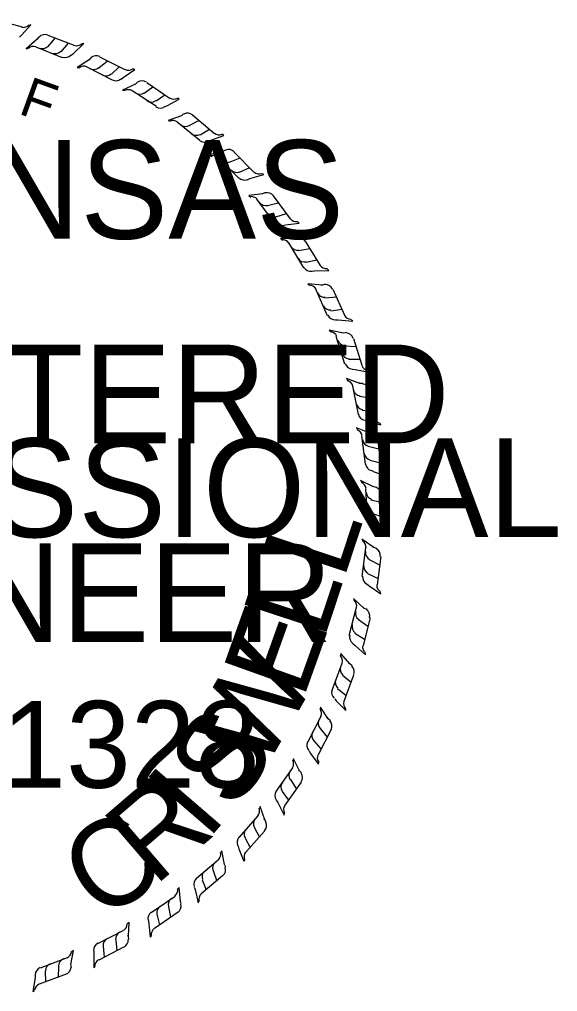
# Model space of a CAD drawing. Extents: x -193 to 149, y 507 to 725.
# Drawn here: x 66.24 to 76.47, y 521.36 to 539.84 of the extents above; entities that cross this region are included whole.
import ezdxf

# ---------------------------------------------------------------- set-up
doc = ezdxf.new("R2010")
doc.units = 0
doc.layers.add('Border 2660-Hwy18 - Stamp-ChrisC', color=7, linetype='Continuous')

msp = doc.modelspace()

# ---------------------------------------------------------------- linework, layer by layer
at = {"layer": 'Border 2660-Hwy18 - Stamp-ChrisC'}
for p, q in [((65.767, 539.835), (66.292, 539.693)), ((66.277, 539.535), (66.457, 539.73)), ((66.457, 539.73), (66.427, 539.723)), ((66.24, 539.498), (66.277, 539.535)), ((66.577, 539.46), (66.367, 539.28)), ((66.577, 539.46), (66.562, 539.445)), ((66.607, 539.505), (66.577, 539.46)), ((66.78, 539.535), (67.29, 539.34)), ((66.78, 539.318), (66.922, 539.483)), ((67.035, 539.22), (67.17, 539.385)), ((66.367, 539.28), (66.42, 539.295)), ((67.057, 539.108), (66.555, 539.31)), ((67.267, 539.19), (67.462, 539.378)), ((67.462, 539.378), (67.425, 539.37)), ((67.23, 539.16), (67.267, 539.19)), ((67.567, 539.07), (67.335, 538.92)), ((67.567, 539.07), (67.537, 539.055)), ((67.597, 539.108), (67.567, 539.07)), ((67.747, 538.913), (67.912, 539.048)), ((67.762, 539.123), (68.242, 538.883)), ((67.335, 538.92), (67.387, 538.913)), ((68.01, 538.68), (67.515, 538.935)), ((67.987, 538.793), (68.137, 538.935)), ((68.212, 538.733), (68.43, 538.883)), ((68.43, 538.883), (68.392, 538.898)), ((68.175, 538.703), (68.212, 538.733)), ((68.482, 538.643), (68.445, 538.605)), ((68.445, 538.605), (68.197, 538.493)), ((68.197, 538.493), (68.242, 538.485)), ((68.842, 538.178), (68.385, 538.478)), ((68.445, 538.605), (68.422, 538.598)), ((68.61, 538.433), (68.775, 538.553)), ((68.662, 538.635), (69.105, 538.335)), ((68.835, 538.29), (69, 538.403)), ((69.052, 538.2), (69.277, 538.32)), ((69.277, 538.32), (69.247, 538.343)), ((69.007, 538.178), (69.052, 538.2)), ((69.322, 538.005), (69.067, 537.915)), ((69.067, 537.915), (69.112, 537.9)), ((69.322, 538.005), (69.3, 537.998)), ((69.36, 538.043), (69.322, 538.005)), ((69.465, 537.818), (69.652, 537.915)), ((69.532, 538.02), (69.945, 537.668)), ((69.667, 537.533), (69.24, 537.885)), ((69.675, 537.645), (69.855, 537.75)), ((69.832, 537.518), (69.877, 537.54)), ((69.877, 537.54), (70.125, 537.63)), ((70.125, 537.63), (70.095, 537.653)), ((70.155, 537.353), (70.11, 537.33)), ((70.11, 537.33), (69.855, 537.263)), ((69.855, 537.263), (69.9, 537.233)), ((70.41, 536.82), (70.02, 537.218)), ((70.11, 537.33), (70.087, 537.315)), ((70.245, 537.128), (70.432, 537.203)), ((70.32, 537.315), (70.695, 536.933)), ((70.425, 536.933), (70.62, 537.023)), ((70.575, 536.79), (70.62, 536.813)), ((70.62, 536.813), (70.882, 536.888)), ((70.882, 536.888), (70.852, 536.903)), ((70.86, 536.52), (70.597, 536.49)), ((70.597, 536.49), (70.635, 536.46)), ((70.86, 536.52), (70.837, 536.513)), ((70.905, 536.543), (70.86, 536.52)), ((71.062, 536.483), (71.385, 536.048)), ((71.085, 535.973), (70.755, 536.423)), ((70.957, 536.303), (71.16, 536.348)), ((71.115, 536.085), (71.317, 536.145)), ((71.242, 535.92), (71.295, 535.935)), ((71.295, 535.935), (71.557, 535.965)), ((71.557, 535.965), (71.527, 535.995)), ((71.52, 535.695), (71.475, 535.673)), ((71.475, 535.673), (71.205, 535.673)), ((71.205, 535.673), (71.242, 535.635)), ((71.647, 535.118), (71.362, 535.59)), ((71.475, 535.673), (71.445, 535.68)), ((71.67, 535.62), (71.955, 535.163)), ((71.55, 535.448), (71.76, 535.485)), ((71.692, 535.223), (71.895, 535.268)), ((71.805, 535.05), (71.85, 535.058)), ((71.85, 535.058), (72.12, 535.065)), ((72.12, 535.065), (72.09, 535.095)), ((72, 534.788), (71.722, 534.81)), ((71.722, 534.81), (71.767, 534.78)), ((72, 534.788), (71.97, 534.788)), ((72.06, 534.803), (72, 534.788)), ((72.097, 534.203), (71.872, 534.713)), ((72.195, 534.713), (72.42, 534.218)), ((72.045, 534.548), (72.27, 534.563)), ((72.157, 534.3), (72.375, 534.33)), ((72.255, 534.128), (72.3, 534.128)), ((72.3, 534.128), (72.577, 534.105)), ((72.577, 534.105), (72.547, 534.135)), ((72.397, 533.873), (72.127, 533.933)), ((72.127, 533.933), (72.172, 533.895)), ((72.397, 533.873), (72.375, 533.88)), ((72.457, 533.888), (72.397, 533.873)), ((72.427, 533.288), (72.262, 533.813)), ((72.592, 533.775), (72.75, 533.265)), ((72.412, 533.633), (72.637, 533.618)), ((72.495, 533.378), (72.712, 533.378)), ((72.57, 533.19), (72.622, 533.183)), ((72.622, 533.183), (72.885, 533.13)), ((72.885, 533.13), (72.862, 533.16)), ((72.712, 532.92), (72.457, 533.01)), ((72.457, 533.01), (72.48, 532.965)), ((72.712, 532.92), (72.69, 532.928)), ((72.765, 532.92), (72.712, 532.92)), ((72.682, 532.328), (72.577, 532.868)), ((72.885, 532.785), (72.99, 532.26)), ((72.705, 532.68), (72.915, 532.643)), ((72.757, 532.41), (72.967, 532.388)), ((72.81, 532.215), (72.855, 532.2)), ((72.855, 532.2), (73.11, 532.133)), ((72.9, 531.975), (72.645, 532.073)), ((72.645, 532.073), (72.667, 532.035)), ((73.11, 532.133), (73.095, 532.155)), ((72.817, 531.383), (72.75, 531.923)), ((72.9, 531.975), (72.87, 531.975)), ((72.952, 531.968), (72.9, 531.975)), ((73.05, 531.825), (73.117, 531.285)), ((72.87, 531.728), (73.072, 531.675)), ((72.9, 531.458), (73.102, 531.413)), ((72.937, 531.263), (72.982, 531.24)), ((72.967, 530.955), (72.72, 531.075)), ((72.72, 531.075), (72.757, 531.038)), ((72.982, 531.24), (73.23, 531.15)), ((73.23, 531.15), (73.222, 531.18)), ((72.855, 530.37), (72.825, 530.918)), ((72.967, 530.955), (72.945, 530.963)), ((73.035, 530.94), (72.967, 530.955)), ((72.922, 530.708), (73.147, 530.655)), ((73.132, 530.798), (73.17, 530.258)), ((72.945, 530.445), (73.155, 530.385)), ((72.967, 530.243), (73.012, 530.22)), ((73.012, 530.22), (73.26, 530.115)), ((73.26, 530.115), (73.245, 530.145)), ((72.975, 529.8), (72.75, 529.958)), ((72.75, 529.958), (72.78, 529.913)), ((72.757, 529.253), (72.825, 529.8)), ((72.975, 529.8), (72.952, 529.815)), ((73.035, 529.785), (72.975, 529.8)), ((73.11, 529.628), (73.042, 529.095)), ((72.885, 529.575), (73.087, 529.47)), ((72.855, 529.305), (73.057, 529.215)), ((72.847, 529.103), (72.885, 529.073)), ((72.885, 529.073), (73.11, 528.923)), ((73.11, 528.923), (73.102, 528.96)), ((72.51, 528.128), (72.645, 528.668)), ((72.795, 528.645), (72.592, 528.833)), ((72.592, 528.833), (72.615, 528.788)), ((72.795, 528.645), (72.78, 528.668)), ((72.855, 528.623), (72.795, 528.645)), ((72.682, 528.435), (72.862, 528.308)), ((72.907, 528.465), (72.772, 527.94)), ((72.615, 528.173), (72.802, 528.06)), ((72.577, 527.978), (72.622, 527.94)), ((72.622, 527.94), (72.817, 527.76)), ((72.352, 527.79), (72.345, 527.745)), ((72.517, 527.588), (72.352, 527.79)), ((72.817, 527.76), (72.817, 527.798)), ((72.187, 527.093), (72.375, 527.603)), ((72.517, 527.588), (72.502, 527.595)), ((72.562, 527.55), (72.517, 527.588)), ((72.382, 527.378), (72.547, 527.243)), ((72.592, 527.378), (72.405, 526.875)), ((72.285, 527.123), (72.45, 526.988)), ((72.232, 526.928), (72.262, 526.89)), ((72.262, 526.89), (72.442, 526.703)), ((71.962, 526.77), (71.955, 526.725)), ((72.105, 526.545), (71.962, 526.77)), ((72.442, 526.703), (72.442, 526.733)), ((71.722, 526.103), (71.977, 526.598)), ((72.105, 526.545), (72.097, 526.568)), ((72.15, 526.508), (72.105, 526.545)), ((72.165, 526.343), (71.917, 525.863)), ((71.955, 526.365), (72.09, 526.2)), ((71.835, 526.125), (71.97, 525.975)), ((71.745, 525.938), (71.767, 525.893)), ((71.452, 525.788), (71.437, 525.743)), ((71.565, 525.555), (71.452, 525.788)), ((71.767, 525.893), (71.925, 525.683)), ((71.925, 525.683), (71.932, 525.72)), ((71.122, 525.165), (71.437, 525.615)), ((71.565, 525.555), (71.55, 525.578)), ((71.602, 525.518), (71.565, 525.555)), ((71.595, 525.345), (71.287, 524.903)), ((71.392, 525.39), (71.505, 525.21)), ((71.235, 525.165), (71.355, 525)), ((71.122, 525), (71.152, 524.955)), ((70.815, 524.88), (70.8, 524.835)), ((70.905, 524.625), (70.815, 524.88)), ((71.152, 524.955), (71.272, 524.715)), ((70.417, 524.288), (70.777, 524.7)), ((70.905, 524.625), (70.89, 524.648)), ((70.927, 524.58), (70.905, 524.625)), ((71.272, 524.715), (71.28, 524.753)), ((70.702, 524.49), (70.8, 524.295)), ((70.53, 524.28), (70.627, 524.1)), ((70.897, 524.408), (70.545, 524.01)), ((70.395, 524.123), (70.41, 524.078)), ((70.41, 524.078), (70.507, 523.838)), ((69.607, 523.515), (70.02, 523.868)), ((70.087, 524.04), (70.065, 524.003)), ((70.14, 523.778), (70.087, 524.04)), ((70.14, 523.778), (70.132, 523.8)), ((70.162, 523.725), (70.14, 523.778)), ((70.507, 523.838), (70.522, 523.86)), ((70.102, 523.56), (69.69, 523.215)), ((69.922, 523.665), (69.99, 523.463)), ((69.277, 523.343), (69.24, 523.305)), ((69.3, 523.073), (69.277, 523.343)), ((69.562, 523.35), (69.577, 523.305)), ((69.712, 523.485), (69.787, 523.298)), ((68.745, 522.863), (69.202, 523.178)), ((69.577, 523.305), (69.637, 523.05)), ((69.075, 522.975), (69.112, 522.78)), ((69.3, 523.073), (69.3, 523.103)), ((69.315, 523.028), (69.3, 523.073)), ((69.637, 523.05), (69.652, 523.073)), ((69.255, 522.87), (68.805, 522.563)), ((68.85, 522.833), (68.902, 522.63)), ((68.325, 522.675), (68.287, 522.645)), ((68.31, 522.413), (68.325, 522.675)), ((68.692, 522.705), (68.7, 522.653)), ((68.7, 522.653), (68.722, 522.398)), ((67.732, 522.278), (68.212, 522.525)), ((68.31, 522.413), (68.302, 522.435)), ((68.317, 522.353), (68.31, 522.413)), ((68.722, 522.398), (68.752, 522.42)), ((68.22, 522.21), (67.747, 521.963)), ((67.83, 522.225), (67.852, 522.015)), ((68.07, 522.345), (68.092, 522.135)), ((67.215, 521.88), (67.267, 522.143)), ((67.267, 522.143), (67.23, 522.113)), ((67.65, 522.128), (67.65, 522.075)), ((67.65, 522.075), (67.65, 521.813)), ((66.637, 521.813), (67.155, 522.008)), ((66.982, 521.843), (66.975, 521.633)), ((67.215, 521.88), (67.222, 521.91)), ((67.23, 521.828), (67.215, 521.88)), ((67.65, 521.813), (67.672, 521.835)), ((66.54, 521.678), (66.54, 521.625)), ((67.125, 521.693), (66.615, 521.505)), ((66.727, 521.753), (66.735, 521.543)), ((66.54, 521.625), (66.495, 521.363)), ((66.495, 521.363), (66.525, 521.385))]:
    msp.add_line(p, q, dxfattribs=at)
for centre, start, end in [((66.314, 539.833), 258.2517, 317.0395), ((66.723, 539.4), 69.0955, 137.4695), ((66.509, 539.176), 73.3563, 132.1441), ((66.673, 539.428), 249.0955, 317.4695), ((66.919, 539.333), 249.0955, 317.4695), ((67.325, 539.483), 253.3563, 312.1441), ((67.111, 539.26), 249.0955, 317.4695), ((67.697, 538.998), 63.0708, 131.4448), ((67.461, 538.798), 67.3316, 126.1194), ((67.65, 539.031), 243.0708, 311.4448), ((68.305, 539.018), 247.3316, 306.1194), ((67.885, 538.911), 243.0708, 311.4448), ((68.069, 538.818), 243.0708, 311.4448), ((68.57, 538.523), 56.1736, 124.5476), ((68.312, 538.353), 60.4344, 119.2222), ((68.527, 538.562), 236.1736, 304.5476), ((68.746, 538.414), 236.1736, 304.5476), ((69.175, 538.47), 240.4344, 299.2222), ((68.917, 538.3), 236.1736, 304.5476), ((69.161, 537.766), 54.451, 113.2388), ((69.436, 537.908), 50.1902, 118.5642), ((69.398, 537.951), 230.1902, 298.5642), ((69.6, 537.781), 230.1902, 298.5642), ((69.758, 537.65), 230.1902, 298.5642), ((70.033, 537.792), 234.451, 293.2388), ((70.216, 537.217), 44.9655, 113.3394), ((69.93, 537.101), 49.2262, 108.0141), ((70.182, 537.263), 224.9655, 293.3394), ((70.368, 537.076), 224.9655, 293.3394), ((70.514, 536.931), 224.9655, 293.3394), ((70.8, 537.047), 229.2262, 288.0141), ((70.648, 536.321), 40.9505, 99.7383), ((70.948, 536.395), 36.6897, 105.0637), ((70.92, 536.446), 216.6897, 285.0637), ((71.078, 536.234), 216.6897, 285.0637), ((71.201, 536.069), 216.6897, 285.0637), ((71.501, 536.143), 220.9505, 279.7383), ((71.548, 535.547), 31.7427, 100.1166), ((71.242, 535.499), 36.0034, 94.7913), ((71.525, 535.6), 211.7427, 280.1166), ((71.663, 535.374), 211.7427, 280.1166), ((72.077, 535.248), 216.0034, 274.7913), ((71.772, 535.2), 211.7427, 280.1166), ((71.749, 534.637), 29.1451, 87.9329), ((72.057, 534.648), 24.8843, 93.2583), ((72.041, 534.704), 204.8843, 273.2583), ((72.151, 534.463), 204.8843, 273.2583), ((72.238, 534.277), 204.8843, 273.2583), ((72.547, 534.288), 209.1451, 267.9329), ((72.133, 533.757), 22.0938, 80.8817), ((72.441, 533.73), 17.8331, 86.207), ((72.432, 533.787), 197.8331, 266.207), ((72.512, 533.535), 197.8331, 266.207), ((72.575, 533.34), 197.8331, 266.207), ((72.883, 533.313), 202.0938, 260.8817), ((72.435, 532.829), 15.7912, 74.579), ((72.735, 532.826), 191.5304, 259.9044), ((72.738, 532.768), 11.5304, 79.9044), ((72.787, 532.566), 191.5304, 259.9044), ((72.828, 532.365), 191.5304, 259.9044), ((73.131, 532.305), 195.7912, 254.579), ((72.609, 531.898), 11.4348, 70.2227), ((72.908, 531.872), 187.174, 255.548), ((72.907, 531.814), 7.174, 75.548), ((72.94, 531.609), 187.174, 255.548), ((72.967, 531.406), 187.174, 255.548), ((73.264, 531.322), 191.4348, 250.2227), ((72.684, 530.9), 8.033, 66.8208), ((72.976, 530.799), 3.7722, 72.1462), ((72.981, 530.857), 183.7722, 252.1462), ((72.997, 530.593), 183.7722, 252.1462), ((73.011, 530.388), 183.7722, 252.1462), ((73.303, 530.287), 188.033, 246.8208), ((72.682, 529.802), 357.57, 56.3579), ((72.951, 529.649), 353.3093, 61.6832), ((72.966, 529.705), 173.3093, 241.6832), ((72.934, 529.442), 173.3093, 241.6832), ((72.911, 529.238), 173.3093, 241.6832), ((73.18, 529.086), 177.57, 236.3579), ((72.504, 528.687), 350.445, 49.2329), ((72.774, 528.556), 166.1842, 234.5582), ((72.752, 528.503), 346.1842, 54.5582), ((72.71, 528.3), 166.1842, 234.5582), ((72.662, 528.1), 166.1842, 234.5582), ((72.91, 527.916), 170.445, 229.2329), ((72.23, 527.647), 344.1611, 42.9489), ((72.484, 527.487), 159.9003, 228.2743), ((72.457, 527.436), 339.9003, 48.2743), ((72.392, 527.239), 159.9003, 228.2743), ((72.322, 527.046), 159.9003, 228.2743), ((72.549, 526.836), 164.1611, 222.9489), ((71.833, 526.65), 337.1149, 35.9028), ((72.065, 526.46), 152.8541, 221.2281), ((72.031, 526.413), 332.8541, 41.2281), ((71.944, 526.225), 152.8541, 221.2281), ((71.85, 526.042), 152.8541, 221.2281), ((71.304, 525.691), 329.7262, 28.514), ((72.049, 525.806), 157.1149, 215.9028), ((71.51, 525.472), 145.4654, 213.8394), ((71.471, 525.43), 325.4654, 33.8394), ((71.244, 525.086), 145.4654, 213.8394), ((71.359, 525.255), 145.4654, 213.8394), ((70.656, 524.793), 322.7822, 21.57), ((71.41, 524.825), 149.7262, 208.514), ((70.834, 524.551), 138.5214, 206.8953), ((70.659, 524.354), 138.5214, 206.8953), ((70.79, 524.514), 318.5214, 26.8953), ((70.523, 524.2), 138.5214, 206.8953), ((69.917, 523.974), 314.7826, 13.5704), ((70.657, 523.921), 142.7822, 201.57), ((70.06, 523.711), 130.5218, 198.8958), ((70.011, 523.68), 310.5218, 18.8958), ((69.702, 523.406), 130.5218, 198.8958), ((69.858, 523.54), 130.5218, 198.8958), ((69.101, 523.293), 308.9134, 7.7012), ((69.216, 523.015), 124.6526, 193.0266), ((69.796, 523.111), 134.7826, 193.5704), ((68.998, 522.866), 124.6526, 193.0266), ((69.164, 522.99), 304.6526, 13.0266), ((68.829, 522.749), 124.6526, 193.0266), ((68.138, 522.65), 301.0994, 359.8872), ((68.215, 522.36), 116.8386, 185.2126), ((68.892, 522.446), 128.9134, 187.7013), ((67.795, 522.148), 116.8386, 185.2126), ((67.978, 522.242), 116.8386, 185.2126), ((68.16, 522.342), 296.8386, 5.2126), ((67.083, 522.141), 294.7331, 353.521), ((66.879, 521.752), 110.4724, 178.8463), ((67.127, 521.844), 110.4724, 178.8463), ((67.817, 521.84), 121.0994, 179.8872), ((66.687, 521.68), 110.4724, 178.8463), ((67.071, 521.832), 290.4724, 358.8463), ((66.674, 521.371), 114.7331, 173.521)]:
    msp.add_arc(centre, 0.148, start, end, dxfattribs=at)

# ---------------------------------------------------------------- texts
for s, height, rotation, p in [('F', 0.75, 340.0707, (66.197, 538.053)), ('L', 1.642, 71.6828, (72.398, 529.166)), ('L', 1.642, 71.6828, (72.021, 528.027)), ('E', 1.642, 70.3031, (71.627, 526.895)), ('W', 1.642, 60.0948, (70.868, 525.514)), ('S', 1.642, 53.9956, (70.301, 524.761)), ('I', 1.642, 49.2381, (69.805, 524.217)), ('R', 1.642, 40.6231, (68.8, 523.346)), ('C', 1.642, 32.5951, (67.755, 522.678))]:
    msp.add_text(s, height=height, rotation=rotation, dxfattribs=at).set_placement(p)
for s, height, p in [('ARKANSAS', 1.875, (58.757, 535.668)), ('REGISTERED', 1.875, (58.12, 531.783)), ('PROFESSIONAL', 1.87497, (57.047, 529.998)), ('ENGINEER', 1.875, (59.095, 528.003)), ('No. 11328', 1.65, (60.626, 525.236))]:
    msp.add_text(s, height=height, dxfattribs=at).set_placement(p)

doc.saveas('drawing.dxf')
